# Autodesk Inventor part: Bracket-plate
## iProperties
Shininess: 64.0
Length Units: 11269
Angle Units: 11279
Time Units: 11290
Mass Units: 11283
Length Display Precision: 3
Angle Display Precision: 2
Compacted: True
Part Number: Bracket-plate
Document SubType Name: Modeling
Created: 2003-01
Designer: Owner
Density: 0.0
Volumn: 0.0
Area: 0.0
PropertySet Name: Model Information
Control State: 0
Master: False
Checked Out: False
Author: Owner
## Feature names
1. Extrusion1
